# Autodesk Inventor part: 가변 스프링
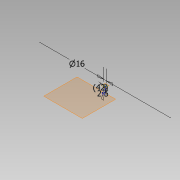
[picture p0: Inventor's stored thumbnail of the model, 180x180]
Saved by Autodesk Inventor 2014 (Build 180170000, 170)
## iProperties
Created: 2015-05
Part Number: 가변 스프링
Material: Generic
Document SubType Name: Modeling
Designer: Administrator
Density: 1 g/cm^3
Appearance: Default
Mass: 1.46208 g
Surface Area: 23.7473 cm^2
Volume: 1.46208 cm^3
Author: Administrator
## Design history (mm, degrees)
sketch "스케치1"
  geometry: L1 (0, 0)-(-8, 0); L2 (-8, 0)-(-8, 42); L3 (-8, 42)-(0, 42); L4 (0, 42)-(0, 0); C1 r 1.25 at (-8, 0)
  constraints: 8 end point, 2 parallel, 1 centre point, 1 coincident, 1 horizontal, 1 perpendicular, 1 other
  dimensions: "d0" = 16 diameter of L2 L4; "d1" = 42 distance between parallel lines of L1 L3 (derived); "d2" = 2.5 diameter of C1
feature "코일1" pitch "d3" = 10; turns "d5" = 6; dims "d4" = 42 (= d1), "d6" = 0, angle "d7" = 90 deg, angle "d8" = 90 deg, "d9" = 0, "d10" = 0
node "작업 평면1"
node "작업 평면2"
sketch "스케치3"
  geometry: L1 (-9.25, 0)-(-6.75, 0) reference
  constraints: 1 horizontal alignment
extrude "돌출2" cut sketch "스케치3" stored distance "d13" = 10; taper "d14" = 0 deg
node "작업 평면3"
sketch "스케치4"
  geometry: L1 (-6.75, 0)-(-9.25, 0) reference
  constraints: 1 horizontal alignment
extrude "돌출3" cut sketch "스케치4" stored distance "d15" = 10; taper "d16" = 0 deg
node "솔리드1"
node "절단 모서리 투영2"
node "절단 모서리 투영3"
